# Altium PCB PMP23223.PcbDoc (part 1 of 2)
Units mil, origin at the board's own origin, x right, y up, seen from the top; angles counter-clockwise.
Board outline 2732.07 x 1574.8 mil, 4 copper layers (Top Layer 1, GND plane, Bottom Layer, Bottom Layer 1), stack 70.356 mil thick; 100 components, 33 nets, 239 pads, 115 vias.
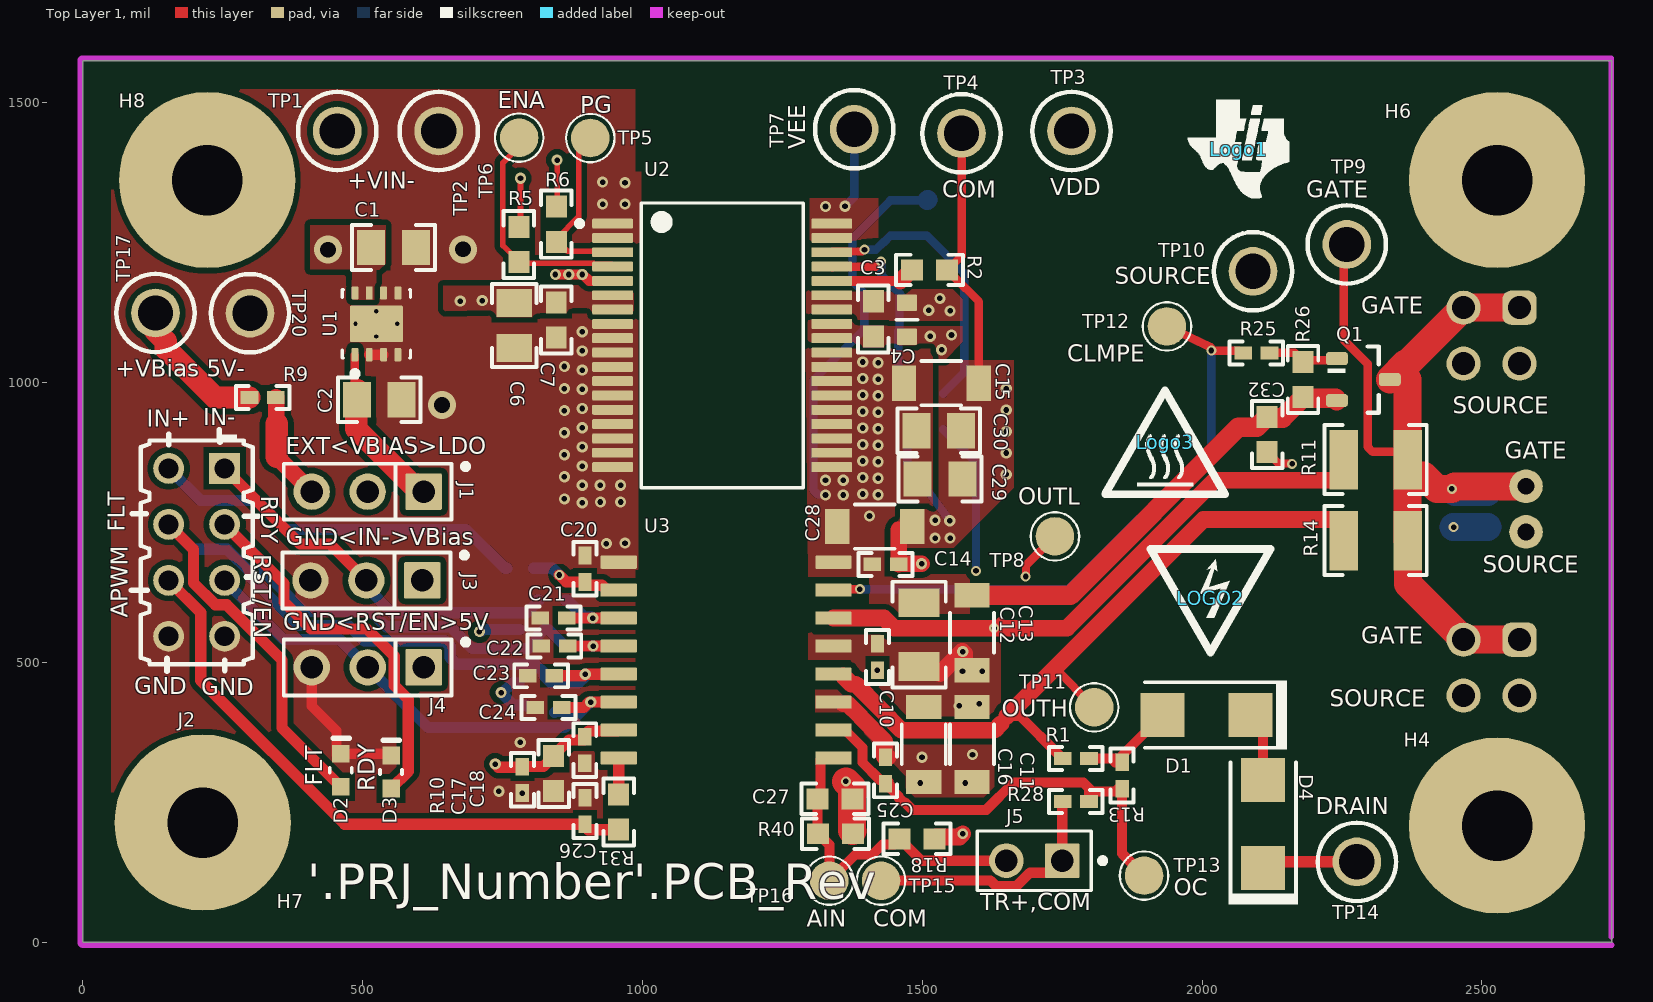
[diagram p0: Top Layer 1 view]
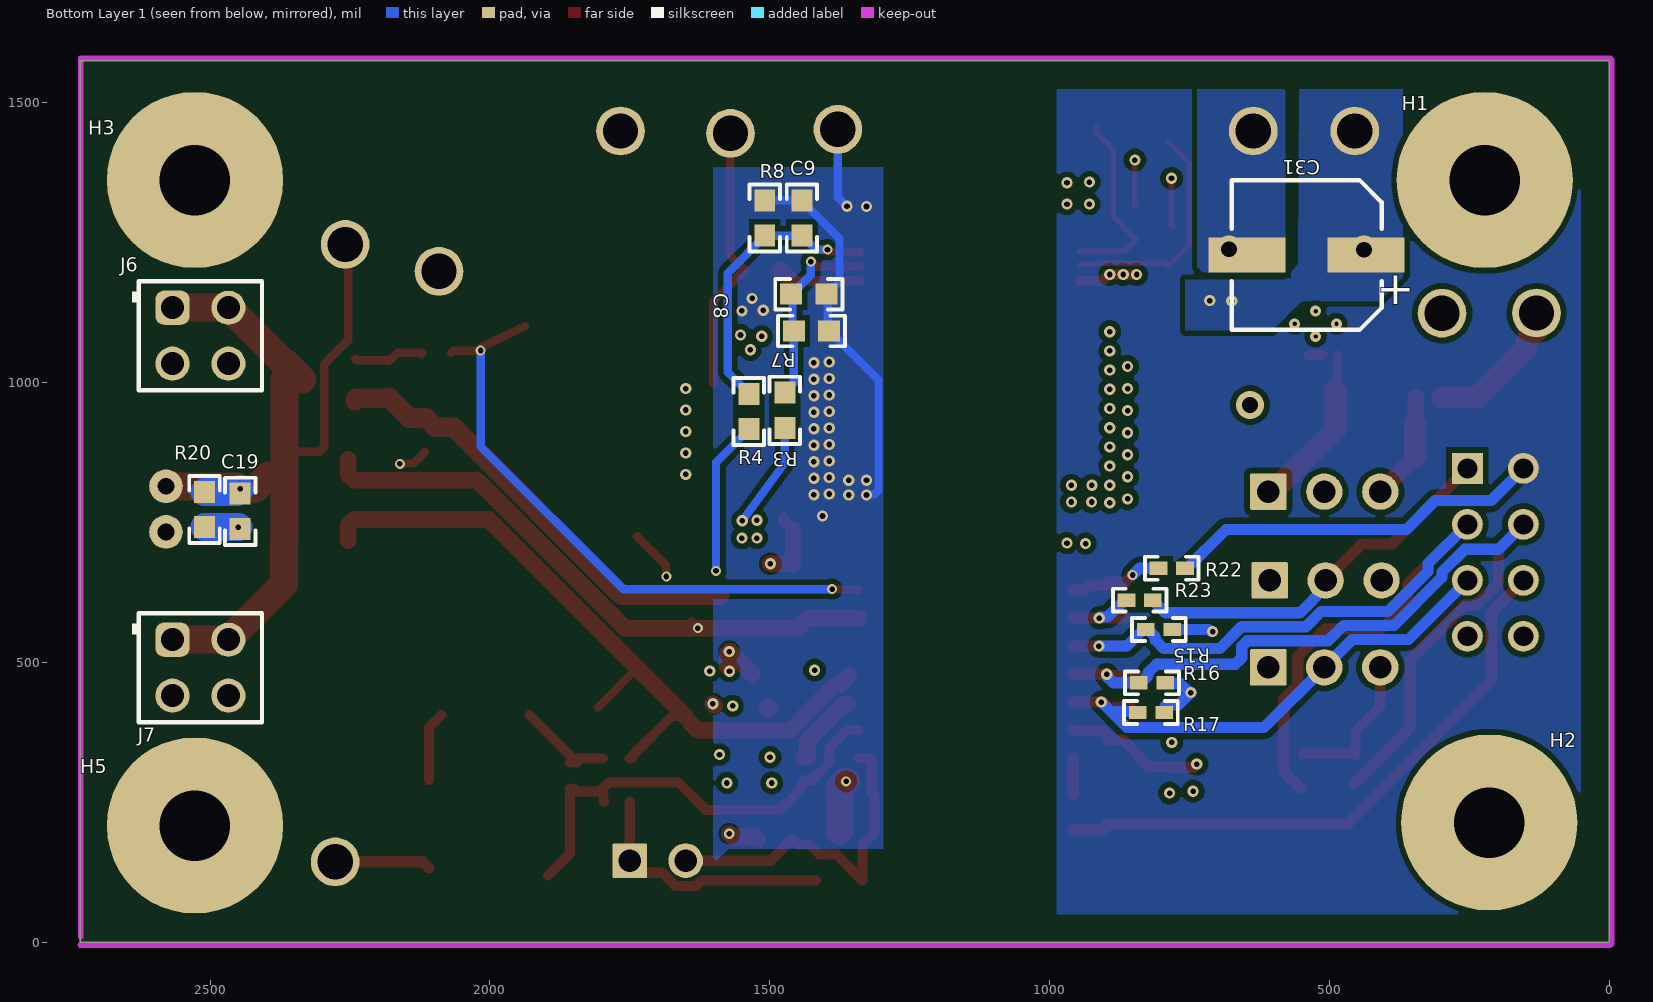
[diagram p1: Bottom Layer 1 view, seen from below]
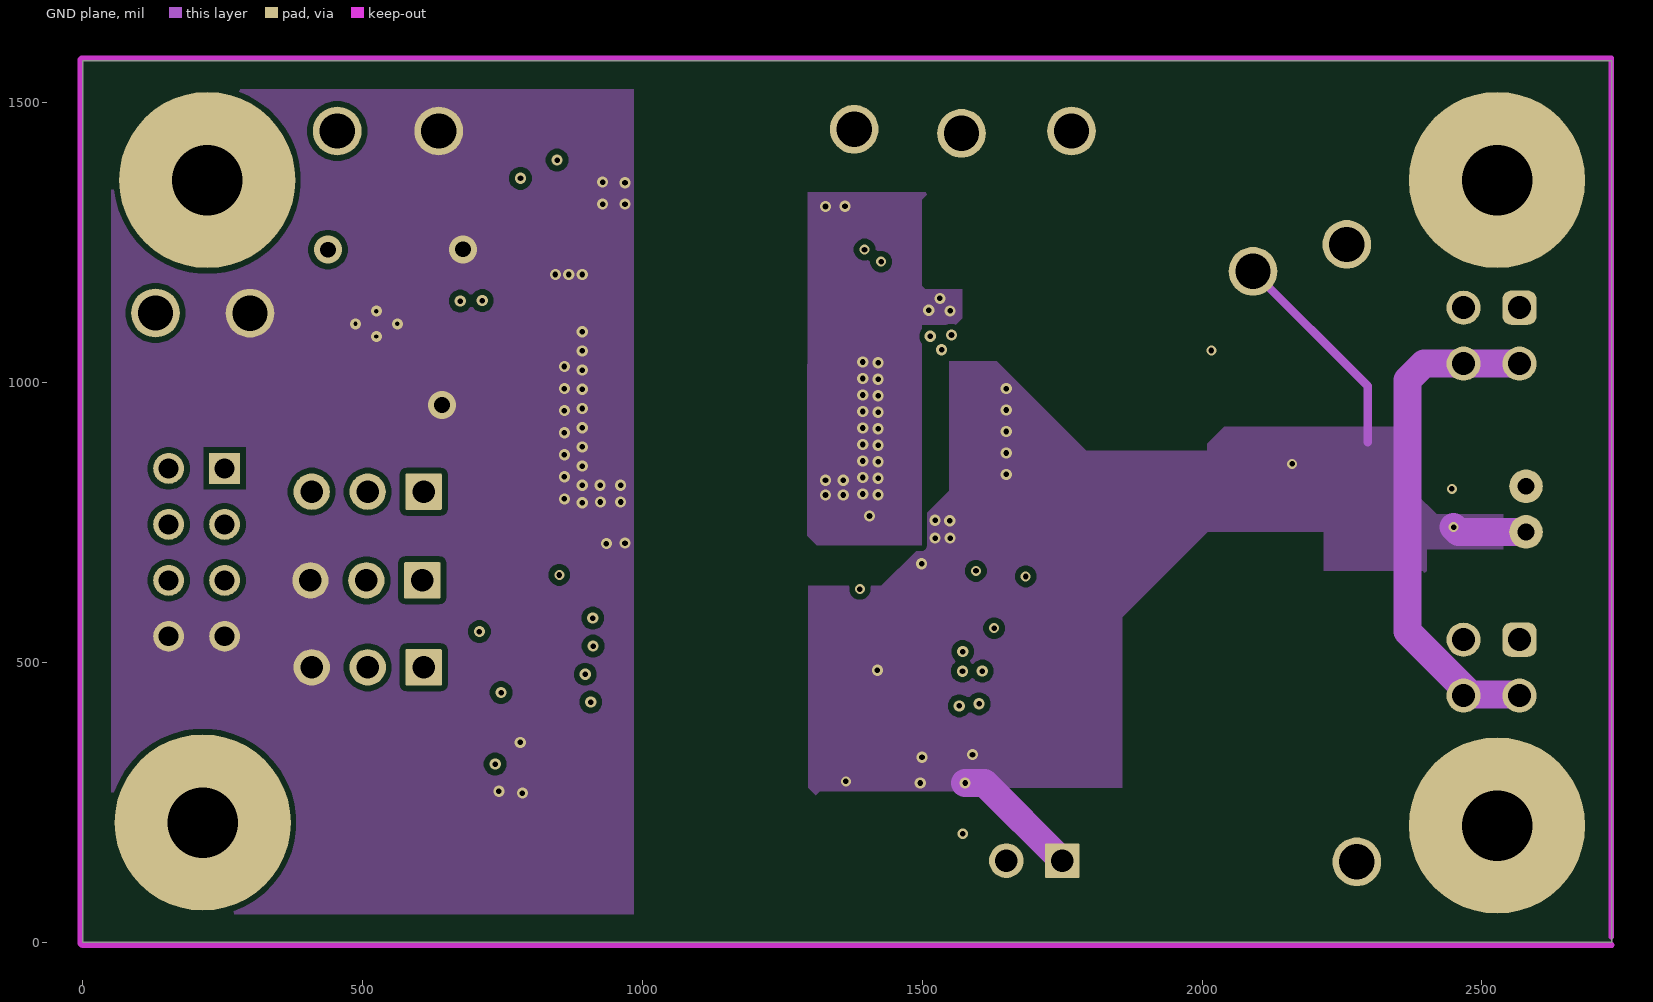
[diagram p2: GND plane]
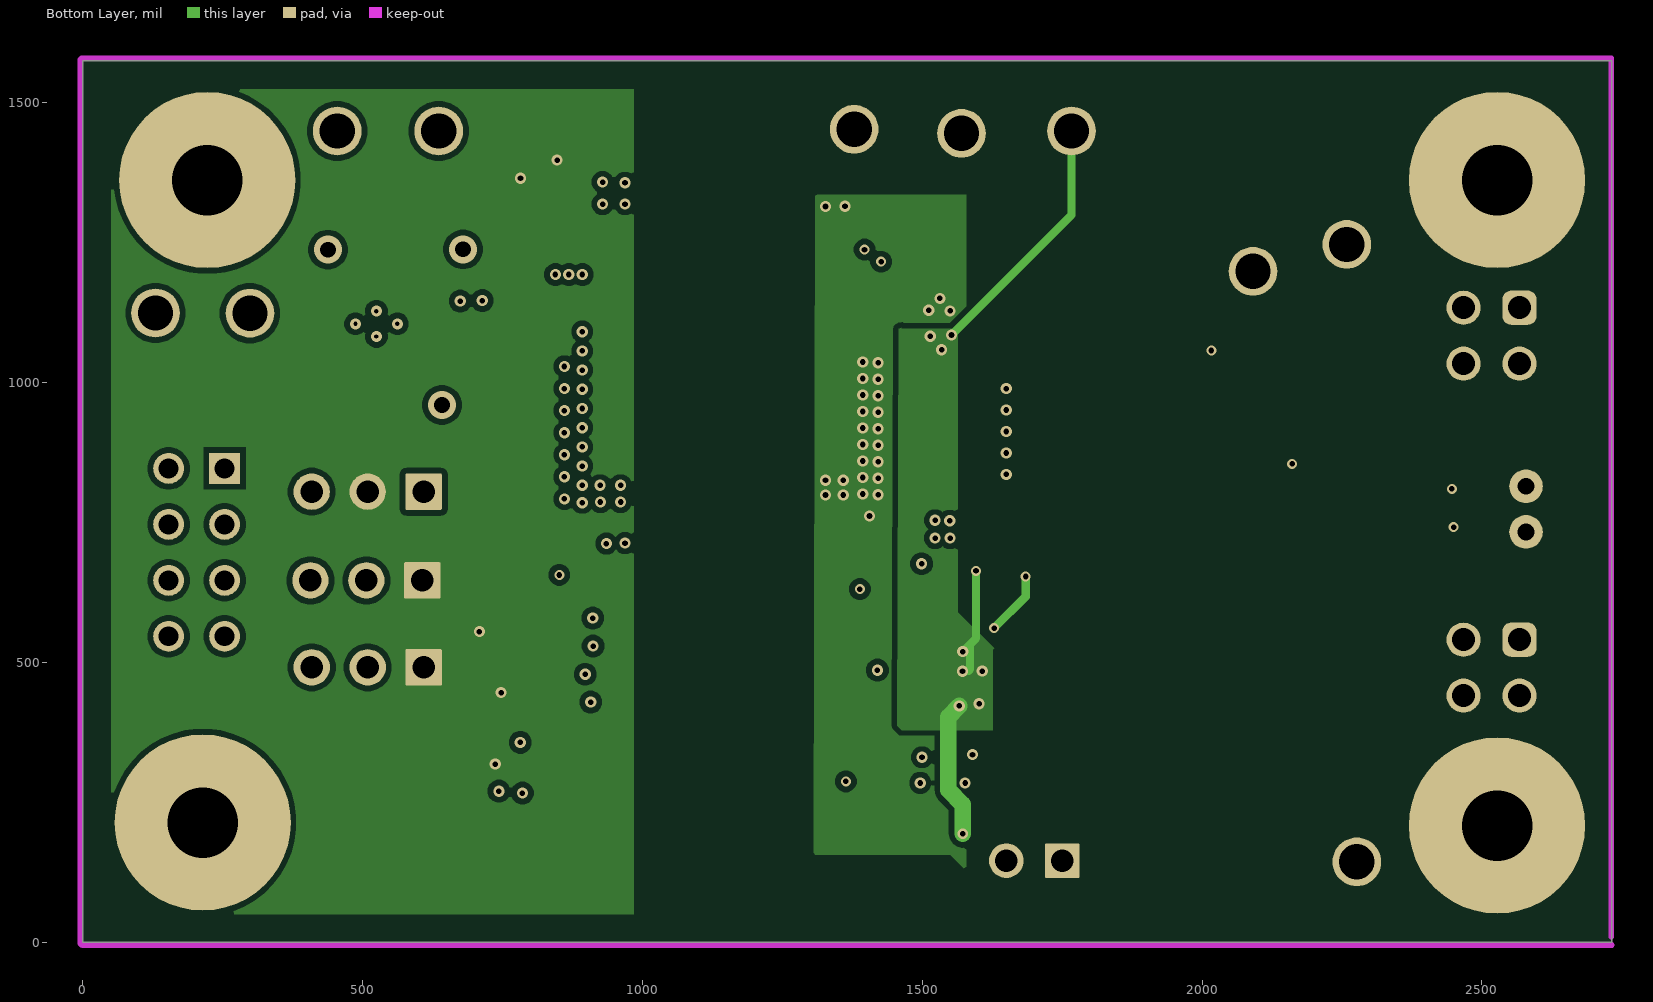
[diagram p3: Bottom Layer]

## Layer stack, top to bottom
Top Solder: solder mask 0.4, Solder Resist, Dk 3.5
Top Layer 1: signal copper 1.378
Dielectric 1: prepreg 2.8, PP-006, Dk 4.1
GND plane: signal copper 1.4
Dielectric1: core 59.2, FR-4 High Tg, Dk 4.8
Bottom Layer: signal copper 1.4
Dielectric 2: prepreg 2.8, PP-006, Dk 4.1
Bottom Layer 1: signal copper 1.378
Bottom Solder: solder mask 0.4, Solder Resist, Dk 3.5

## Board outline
0,0 0,1574.8 2732.07,1574.8 2732.07,0

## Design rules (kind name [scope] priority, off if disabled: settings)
AcuteAngle [All] p1: minimum=4.50000000000000E+0001 checktracksonly=TRUE
AssemblyTestPointUsage [All] p1: valid=2
BoardOutlineClearance BoardOutlineClearance_MountingHoles [OnCopper and InComponentClass('Mounting Holes')] p1: gap=39.37 ignorepadtopadclearanceinfootprint=FALSE
BoardOutlineClearance BoardOutlineClearance_Poly [OnCopper and IsPoly] p2: gap=50 ignorepadtopadclearanceinfootprint=FALSE
BoardOutlineClearance [OnCopper and Not InComponentClass('Logo') and not InComponentClass('FiducialMark') and not InRegion(1000,500,4000,800) and not InPoly] p3: gap=75 ignorepadtopadclearanceinfootprint=FALSE
Clearance Clearance_Keepouts [((IsTrack Or IsArc) And Not InPoly) And IsFree and IsKeepOut vs ((IsTrack Or IsArc) And Not InPoly) And IsFree and IsKeepOut] p1: gap=0 ignorepadtopadclearanceinfootprint=FALSE
Clearance Clearance_Poly [InPolygon] p2: gap=10 ignorepadtopadclearanceinfootprint=TRUE
Clearance Clearance_FiducialMark [IsKeepOut and InComponentClass('FiducialMark') vs IsPad and InComponentClass('FiducialMark')] p3: gap=0 ignorepadtopadclearanceinfootprint=FALSE
Clearance [All] p4: gap=5 ignorepadtopadclearanceinfootprint=TRUE
ComponentClearance ComponentClearance_2 [InComponent('NT*')] p1: gap=0 collisioncheckmode=3 verticalgap=0 showdistances=FALSE
ComponentClearance ComponentClearance_MountingHoles_FiducialMarks [InComponentClass('Mounting Holes') vs InComponentClass('FiducialMark')] p2: gap=50 collisioncheckmode=3 verticalgap=10 showdistances=FALSE
ComponentClearance ComponentClearance_Shunt [InComponentClass('Header') vs InComponentClass('Shunt')] p3: gap=0 collisioncheckmode=3 verticalgap=0 showdistances=FALSE
ComponentClearance ComponentClearance_Logo [InComponentClass('Logo')] p4: gap=50 collisioncheckmode=3 verticalgap=10 showdistances=FALSE
ComponentClearance ComponentClearance_ScrewToNut [(HasFootprint('NY PMS 440 0025 PH')) vs (HasFootprint('Keystone_1902C'))] p5: gap=5 collisioncheckmode=3 verticalgap=10 showdistances=FALSE
ComponentClearance ComponentClearance_MountingHoles [InComponentClass('Mounting Holes')] p6: gap=250 collisioncheckmode=3 verticalgap=100000 showdistances=FALSE
ComponentClearance ComponentClearance_SmallPassives [HasFootprint('0201*') or HasFootprint('0402*') or HasFootprint('0508') or HasFootprint('0603*') or HasFootprint('0612') or HasFootprint('0805*') or HasFootprint('0815*') or HasFootprint('0830*') or HasFootprint('1206*') or HasFootprint('1210*') or HasFootprint('1808*') or HasFootprint('1812*') or HasFootprint('1825*') or HasFootprint('2010*') or HasFootprint('2220*') or HasFootprint('2225*') or HasFootprint('2512*') or HasFootprint('2728*') or HasFootprint('3518*') vs HasFootprint('0201*') or HasFootprint('0402*') or HasFootprint('0508') or HasFootprint('0603*') or HasFootprint('0612') or HasFootprint('0805*') or HasFootprint('0815*') or HasFootprint('0830*') or HasFootprint('1206*') or HasFootprint('1210*') or HasFootprint('1808*') or HasFootprint('1812*') or HasFootprint('1825*') or HasFootprint('2010*') or HasFootprint('2220*') or HasFootprint('2225*') or HasFootprint('2512*') or HasFootprint('2728*') or HasFootprint('3518*')] p7: gap=14.96 collisioncheckmode=3 verticalgap=10 showdistances=FALSE
ComponentClearance ComponentClearance_THtoSMT [IsThruComponent vs IsSMTComponent] p8: gap=40 collisioncheckmode=3 verticalgap=30 showdistances=FALSE
ComponentClearance ComponentClearance_THtoTH [IsThruComponent vs IsThruComponent] p9: gap=30 collisioncheckmode=3 verticalgap=30 showdistances=FALSE
ComponentClearance [All] p10: gap=30 collisioncheckmode=3 verticalgap=10 showdistances=FALSE
DiffPairsRouting [All] p1: maxlimit=100 minlimit=10 mostfreqgap=10 toplayer_minwidth=6 toplayer_maxwidth=15 toplayer_prefwidth=6 midlayer1_minwidth=6 midlayer1_maxwidth=15 midlayer1_prefwidth=6 midlayer2_minwidth=6 midlayer2_maxwidth=15 midlayer2_prefwidth=6 bottomlayer_minwidth=6 bottomlayer_maxwidth=15 bottomlayer_prefwidth=6 maxuncoupledlength=1000
FabricationTestPointUsage TestPointUsage [All] p1: valid=2 allowmultiple=FALSE
FabricationTestpoint Testpoint [All] p1: side=3 testpointundercomponent=TRUE minsize=40 maxsize=100 preferedsize=60 minholesize=0 maxholesize=40 preferedholesize=32 testpointgrid=1 allowsidetop=TRUE allowsidebottom=TRUE usegrid=TRUE gridtolerance=0.01
FanoutControl Fanout_LCC [IsLCC] p1: bgadir=Out bgaviamode=Centered fanoutstyle=Auto fanoutdirection=Alternating viagrid=1 // Fanout_LCC (Default Rule)
FanoutControl Fanout_BGA [IsBGA] p2: bgadir=Out bgaviamode=Centered fanoutstyle=Auto fanoutdirection=Alternating viagrid=1 // Fanout_BGA (Default Rule)
FanoutControl Fanout_Default [All] p4: bgadir=Out bgaviamode=Centered fanoutstyle=Auto fanoutdirection=Alternating viagrid=1 // Fanout_Default (Default Rule)
FanoutControl Fanout_Small [(CompPinCount < 5)] p5: bgadir=Out bgaviamode=Centered fanoutstyle=Auto fanoutdirection=OutThenIn viagrid=1 // Fanout_Small (Default Rule)
HoleSize [All] p1: absolutevalues=TRUE maxlimit=270 minlimit=7.87 maxpercent=80.000 minpercent=20.000
MinimumAnnularRing MinimumAnnularRing_ThermalPadVias [IsVia and InAnyComponent] p1: minimumring=5.91
MinimumAnnularRing [All] p2: minimumring=4
MinimumSolderMaskSliver MinimumSolderMaskSliver_Logo [InComponentClass('Logo') vs InComponentClass('Logo')] p1: minsoldermaskwidth=0.7
MinimumSolderMaskSliver [All] p2: minsoldermaskwidth=1.5
NetsToIgnore [InNet('No Net')] p1 off:
PlaneClearance [All] p1: clearance=10
PlaneConnect [All] p1: planeconnectstyle=Relief reliefexpansion=10 reliefentries=4 reliefconductorwidth=10 reliefairgap=10
PolygonConnect [All] p1: connectstyle=Direct reliefconductorwidth=10 reliefentries=4 polygonreliefangle="90 Angle" airgapwidth=10
RoutingVias ThermalPadVias [IsVia and InAnyComponent] p1: holewidth=7.87 width=19.68 viastyle="Through Hole" minholewidth=7.87 minwidth=19.68 maxholewidth=12.99 maxwidth=23.62
RoutingVias [All] p2: holewidth=10 width=18 viastyle="Through Hole" minholewidth=10 minwidth=18 maxholewidth=40 maxwidth=64
SMDEntry [All] p1 off: side=TRUE corner=TRUE anyangle=FALSE
SMDToCorner [All] p1 off: distance=50000
SilkToBoardRegionClearance [Not ((IsComment or IsDesignator) And (Hide <> 'False')) and not InRegion(1000,500,4000,800)] p1:
SilkToSilkClearance SilkToSilkClearance_Pb-FreeLogo [(HasFootprint('Pb-Free_Overlay_Medium') OR HasFootprint('Pb-Free_Overlay_Small')) vs (HasFootprint('Pb-Free_Overlay_Medium') OR HasFootprint('Pb-Free_Overlay_Small'))] p1: silktosilkclearance=0
SilkToSilkClearance [All] p2: silktosilkclearance=0
SilkToSolderMaskClearance SilkToComponentPadClearance [(IsPad or IsFill or IsRegion) and InAnycomponent] p1: minsilkscreentomaskgap=3 clearancetoexposedcopper=TRUE
SilkToSolderMaskClearance "Silk to Solder Mask Opening" [All] p2: minsilkscreentomaskgap=3.94 clearancetoexposedcopper=FALSE
SolderMaskExpansion [All] p1: expansion=4 istentingtop=FALSE
UnRoutedNet [All] p1: checkbadconnections=TRUE
Width [All] p1: maxlimit=100 minlimit=5 preferedwidth=10 checkconnectedcopper=TRUE
13 further rules are at their usual default settings.

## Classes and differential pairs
component class Logo: Logo1
component class "Mounting Holes": H4 H6 H7 H8
component class Header: J1 J2 J3 J4

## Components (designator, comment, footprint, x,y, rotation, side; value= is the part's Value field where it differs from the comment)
C1 "CGA4J3X7R1H105K125AB" 0805_HV 554.98,1241.36 r0 top value=1uF
C2 "GCJ21BR71A106KE01L" 0805_HV 529.53,969.45 r0 top value=10uF
C3 "CGA3E2X7R1H104K080AA" 0603 1412.48,1113.91 r90 top value=0.1uF
C4 "GRT188C8YA225KE13D" FP-GRT188C8YA225KE13D_0603-MFG 1472.5,1112.41 r270 top value=2.2µF
C6 "CGA4J1X7R1V475K125AC" 0805_HV 770.77,1101.92 r270 top value=4.7uF
C7 "CGA3E2X7R1H104K080AA" 0603 845.76,1112.1 r270 top value=0.1uF
C8 "GRM188R72A331KA01D" 0603 1429.96,1158.21 r180 bottom value=330pF
C9 "GRM188R72A331KA01D" 0603 1442.22,1294.24 r90 bottom value=330pF
C10 "GCM155R71C104KA55D" 0402 1419.72,509.76 r270 top value=0.1uF
C11 "CL31B106KBHNNNE" 1206_180 1588.82,353.47 r270 top value=10uF
C12 "C1206C104J5RACTU" 1206 1494.1,549.68 r90 top value=0.1uF
C13 "C3216X7R1H475K160AC" 1206_180 1588.82,552.94 r90 top value=4.7uF
C14 "GCM155R71C104KA55D" 0402 1434.13,675.29 r180 top value=0.1uF
C15 "CL31B106KBHNNNE" 1206_180 1534.03,999.06 r180 top value=10uF
C16 "CL31B106KBHNNNE" 1206_180 1502.61,353.47 r270 top value=10uF
C17 "C1608X7R1A155K080AC" 0603 841.02,301.43 r90 top value=1.5uF
C18 "Capacitor" 0402 896.78,343.35 r270 top value=0.1uF
C19 "C1608X7R1H103K080AA" 0603 2446.26,770.01 r270 bottom value=0.01uF
C20 "CC0402JRNPO9BN101" 0402 897.16,667.4 r90 top value=100pF
C21 "CC0402JRNPO9BN101" 0402 840.91,579.18 r180 top value=100pF
C22 "CC0402JRNPO9BN101" 0402 842.4,529.18 r180 top value=100pF
C23 "CC0402JRNPO9BN101" 0402 818.77,476.14 r180 top value=100pF
C24 "CC0402JRNPO9BN101" 0402 831.98,419.7 r180 top value=100pF
C25 "GRM1555C1H241JA01D" 0402 1434.13,307.02 r90 top value=240pF
C26 "GRM155R71C222KA01D" 0402 897.16,234.5 r90 top value=2200pF
C27 "SR0603X7R103K1NT95(F)#M123A" 0603 1343.93,256.15 r0 top value=0.01uF
C28 "C3216X7R1H475K160AC" 1206_180 1415.02,742.71 r180 top value=4.7uF
C29 "GRT21BR61E226ME13L" 0805_HV 1531.43,827.68 r180 top value=22uF
C30 "GRT21BR61E226ME13L" 0805_HV 1529.3,914.01 r180 top value=22uF
C31 "HHXC250ARA470MF61G" HXB_F61 540.33,1228.05 r0 bottom value=47uF
C32 "CGA3E2X7R1H104K080AA" 0603 2116.2,907.46 r270 top value=0.1uF
D1 "STTH112A" SMA 2007.82,406.02 r180 top value=1200V
D2 "LG L29K-G2J1-24-Z" "LG L29K_GREEN" 460.79,307.33 r90 top value=Green
D3 "LG L29K-G2J1-24-Z" "LG L29K_GREEN" 550.59,304.19 r90 top value=Green
D4 "STTH112A" SMA 2108.99,211.4 r90 top value=1200V
H1 "1902C" Keystone_1902C 222.12,1361.91 r180 bottom
H2 "1902C" Keystone_1902C 214.06,213.83 r180 bottom
H3 "1902C" Keystone_1902C 2527.04,1361.97 r180 bottom
H4 "NY PMS 440 0025 PH" "NY PMS 440 0025 PH" 2527.04,208.41 r0 top
H5 "1902C" Keystone_1902C 2527.04,208.41 r180 bottom
H6 "NY PMS 440 0025 PH" "NY PMS 440 0025 PH" 2527.04,1361.97 r0 top
H7 "NY PMS 440 0025 PH" "NY PMS 440 0025 PH" 214.06,213.83 r0 top
H8 "NY PMS 440 0025 PH" "NY PMS 440 0025 PH" 222.12,1361.91 r0 top
J1 "HTSW-103-07-G-S" Samtec_HTSW-103-07-G-S 508.78,805.07 r180 top
J2 "802-10-008-10-001000" Mill-Max_802-10-008-10-001000 203.09,696.63 r270 top
J3 "HTSW-103-07-G-S" Samtec_HTSW-103-07-G-S 506.48,646.63 r180 top
J4 "HTSW-103-07-G-S" Samtec_HTSW-103-07-G-S 508.87,491.23 r180 top
J5 "2011-1X02G00SB" FP-2011-1X02G00SB_HDR-MFG 1699.98,145.62 r180 top
J6 "SSW-102-01-G-D" Samtec_SSW-102-01-x-D 2517.13,1083.88 r180 bottom
J7 "SSW-102-01-G-D" Samtec_SSW-102-01-x-D 2517.13,490.63 r180 bottom
Logo1 "Texas Instruments" TI_Symbol_Overlay_Small 2064.98,1416.97 r0 top
LOGO2 "DANGER HIGH VOLTAGE" IEC_HighVoltage_Small 2014.88,614.96 r180 top
Logo3 "CAUTION HOT SURFACE" IEC_HotSurface_Small 1933.67,893.49 r0 top
Q1 "SI2318CDS-T1-GE3" SOT-23 2288.03,1005.51 r0 top value=40V
R1 "RMCF0402FT2K20" 0402 1774.16,328.31 r0 top value=2.20k
R2 "CRCW0603470RJNEA" 0603 1512.72,1201.36 r180 top value=470
R3 "RT0603BRD0713K2L" 0603 1472.89,950.46 r270 bottom value=13.2k
R4 "RT0603DRE0777K7L" 0603 1537.22,948.45 r270 bottom value=77.7k
R5 "CRCW060310K0FKEA" 0603 779.12,1246.75 r90 top value=10.0k
R6 "CRCW060310K0FKEA" 0603 845.94,1283.17 r270 top value=10.0k
R7 "ERJ-3EKF2202V" 0603 1425.27,1092.26 r0 bottom value=22.0k
R8 "CRCW060310K0FKEA" 0603 1508.68,1294.24 r270 bottom value=10.0k
R9 "CRCW04023R30JNED" 0402 321.14,973.52 r0 top value=3.3
R10 "RMCF0402FT10K0" 0402 785.18,290.2 r90 top value=10.0k
R11 "RC1210FR-072R2L" 1210 2310.12,862.43 r0 top value=2.20
R13 "CRCW04026K04FKED" 0402 1857.07,297.94 r270 top value=6.04k
R14 "RC1210FR-072R2L" 1210 2310.12,717.8 r0 top value=2.20
R15 "CRCW04024K99FKED" 0402 804.41,558.68 r180 bottom value=4.99k
R16 "CRCW04024K99FKED" 0402 816.64,463.58 r180 bottom value=4.99k
R17 "PCF0402-12-10KBT1" 0402 818.77,410.29 r180 bottom value=10.0k
R18 "RT0603DRE0725K8L" 0603 1490.22,184.53 r0 top value=25.8k
R20 "CRCW060310K0JNEA" 0603 2509.84,773.22 r90 bottom value=10k
R22 "Resistor" 0402 781.48,668.28 r180 bottom value=100
R23 "Resistor" 0402 838.69,611.14 r180 bottom value=100
R25 "ERJ-2GE0R00X" 0402 2096.75,1053.1 r180 top value=0
R26 "M55342K12B10E0T" 0603 2180.22,1005.51 r90 top value=10.0k
R28 "CRCW0402499RFKED" 0402 1774.16,251.23 r180 top value=499
R31 "RT0603DRE0720KL" 0603 957.28,232.53 r270 top value=20.0k
R40 "CRCW06036K19FKEA" 0603 1344.69,193.86 r180 top value=6.19k
TP1 "VIN" Keystone5005 454.38,1449.65 r0 top
TP2 "GND" Keystone5006 635.75,1449.65 r0 top
TP3 "5005" Keystone5005 1766.55,1449.65 r0 top
TP4 "5006" Keystone5006 1570.09,1445.54 r0 top
TP5 "PG" Mill-Max_0508-0-00-15-00-00-03-0 906.6,1437.11 r90 top
TP6 "ENA" Mill-Max_0508-0-00-15-00-00-03-0 779.41,1437.76 r0 top
TP7 "5007" Keystone5007 1378.21,1452.76 r0 top
TP8 "OUTL" Mill-Max_0508-0-00-15-00-00-03-0 1736.91,725.25 r0 top
TP9 "5009" Keystone5009 2258.41,1247.03 r0 top
TP10 "5006" Keystone5006 2090.87,1198.94 r90 top
TP11 "OUTH" Mill-Max_0508-0-00-15-00-00-03-0 1807.03,419.7 r90 top
TP12 "CLME" Mill-Max_0508-0-00-15-00-00-03-0 1937.08,1100.43 r180 top
TP13 "OC" Mill-Max_0508-0-00-15-00-00-03-0 1896.19,119.08 r90 top
TP14 "5008" Keystone5008 2276.41,143.65 r90 top
TP15 "COM" Mill-Max_0508-0-00-15-00-00-03-0 1426.18,110.01 r90 top
TP16 "AIN" Mill-Max_0508-0-00-15-00-00-03-0 1333.73,110.01 r90 top
TP17 "VBIAS" Keystone5005 129.6,1124.43 r0 top
TP20 "GND" Keystone5006 298.36,1124.02 r0 top
U1 "TPS7B8450QWDRBRQ1" DRB0008J-MFG 524.38,1104.99 r90 top
U2 "UCC14240DWNQ1" DWN0036-MFG 1142.32,1066.6 r0 top
U3 "UCC21732QDWRQ1" DW0016B_HV 1149.21,504.18 r180 top

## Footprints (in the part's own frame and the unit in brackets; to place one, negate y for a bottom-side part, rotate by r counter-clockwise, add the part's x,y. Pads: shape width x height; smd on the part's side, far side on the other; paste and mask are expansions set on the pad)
0402 [mm] "0402 from SM-752 data"
  rect 0.8x0.6 smd: 1(-0.6,0) 2(0.6,0)
  silkscreen extent -1.22,-0.52 1.22,0.52, body extent -0.55,-0.3 0.55,0.3, height 0.6
0603 [mm] "0603 from SM-752 data"
  rect 1x0.95 smd: 1(-0.8,0) 2(0.8,0)
  silkscreen extent -1.52,-0.69 1.52,0.69, body extent -0.87,-0.47 0.87,0.47, height 1
0805_HV [mil] "0805 with 30mil clearance between pads"
  rect 50x63 smd: 1(-40,0) 2(40,0)
  silkscreen extent -74,-40 74,40, body extent -43,-29 43,29, height 57
1206 [mm] "1206 from SM-752 data"
  rect 1.3x1.85 smd: 1(-1.45,0) 2(1.45,0)
  silkscreen extent -2.4,-1.21 2.4,1.21, body extent -1.7,-0.9 1.7,0.9, height 1.35
1206_180 [mm] "1206_180"
  rect 1.1x1.6 smd: 1(-1.7,0) 2(1.7,0)
  silkscreen extent -0.9,-1 0.9,1, body extent -1.75,-0.95 1.75,0.95, height 1.8
1210 [mm] "1210 from SM-752 data"
  rect 1.3x2.7 smd: 1(-1.45,0) 2(1.45,0)
  silkscreen extent -2.32,-1.57 2.32,1.57, body extent -1.7,-1.35 1.7,1.35, height 1.35
DRB0008J-MFG [mm]
  rrect32% 0.6x0.31 smd paste+0 mask+0: 1(-1.4,0.975) 2(-1.4,0.325) 3(-1.4,-0.325) 4(-1.4,-0.975) 5(1.4,-0.975) 6(1.4,-0.325) 7(1.4,0.325) 8(1.4,0.975)
  rrect6% 1.65x2.4 smd paste-1000 mask+0: 9(0,0)
  silkscreen extent -2.38,-1.55 1.55,1.55, body extent -1.8,-1.65 1.8,1.65, height 0.25
DW0016B_HV [mm] "SOIC-16, HV/isolation option"
  rrect17% 1.65x0.6 smd: 1(-4.875,4.445) 2(-4.875,3.175) 3(-4.875,1.905) 4(-4.875,0.635) 5(-4.875,-0.635) 6(-4.875,-1.905) 7(-4.875,-3.175) 8(-4.875,-4.445) 9(4.875,-4.445) 10(4.875,-3.175) 11(4.875,-1.905) 12(4.875,-0.635) 13(4.875,0.635) 14(4.875,1.905) 15(4.875,3.175) 16(4.875,4.445)
  body extent -5.17,-5.15 5.17,5.15, height 2.59
DWN0036-MFG [mm]
  rrect22% 1.85x0.45 smd paste+0 mask+0: 1(-4.975,5.525) 2(-4.975,4.875) 3(-4.975,4.225) 4(-4.975,3.575) 5(-4.975,2.925) 6(-4.975,2.275) 7(-4.975,1.625) 8(-4.975,0.975) 9(-4.975,0.325) 10(-4.975,-0.325) 11(-4.975,-0.975) 12(-4.975,-1.625) 13(-4.975,-2.275) 14(-4.975,-2.925) 15(-4.975,-3.575) 16(-4.975,-4.225) 17(-4.975,-4.875) 18(-4.975,-5.525) 19(4.975,-5.525) 20(4.975,-4.875) 21(4.975,-4.225) 22(4.975,-3.575) 23(4.975,-2.925) 24(4.975,-2.275) 25(4.975,-1.625) 26(4.975,-0.975) 27(4.975,-0.325) 28(4.975,0.325) 29(4.975,0.975) 30(4.975,1.625) 31(4.975,2.275) 32(4.975,2.925) 33(4.975,3.575) 34(4.975,4.225) 35(4.975,4.875) 36(4.975,5.525)
  silkscreen extent -6.6,-6.47 3.67,6.47, body extent -6,-6.57 6,6.57, height 0.25
FP-2011-1X02G00SB_HDR-MFG [mm]
  rrect6% 1.57x1.57 hole 1.02 paste-1000 mask+0: 1(-1.27,0)
  round 1.57 hole 1.02 paste-1000 mask+0: 2(1.27,0)
  silkscreen extent -3.22,-1.35 2.59,1.35, body extent -2.69,-1.45 2.69,1.45, height 0.25
FP-GRT188C8YA225KE13D_0603-MFG [mm]
  rrect13% 0.75x0.9 smd paste+0 mask+0: 1(-0.775,0) 2(0.775,0)
  silkscreen extent 0,-0.5 0,0.5, body extent -1.25,-0.6 1.25,0.6, height 0.25
HXB_F61 [mm] "SMD, 2-Leads, Dia 6.3mm"
  rect 3.5x1.6 smd: 1(-2.7,0) 2(2.7,0)
  silkscreen extent -3.4,-3.4 3.4,3.4, body extent -3.4,-3.4 3.4,3.4, height 6.11
IEC_HighVoltage_Small [mil]
  silkscreen extent -107,-88 107,97
IEC_HotSurface_Small [mil]
  silkscreen extent -107,-93 107,92
Keystone5005 [mil] "Keystone Compact loops"
  round 87 hole 63: 1(0,0)
  silkscreen extent -70,-70 70,70, body extent -63,-63 62,63, height 225
Keystone5006 [mil] "Keystone Compact loops"
  round 87 hole 63: 1(0,0)
  silkscreen extent -70,-70 70,70, body extent -63,-63 62,63, height 225
Keystone5007 [mil] "Keystone Compact loops"
  round 87 hole 63: 1(0,0)
  silkscreen extent -70,-70 70,70, body extent -63,-63 62,63, height 225
Keystone5008 [mil] "Keystone Compact loops"
  round 87 hole 63: 1(0,0)
  silkscreen extent -70,-70 70,70, body extent -63,-63 62,63, height 225
Keystone5009 [mil] "Keystone Compact loops"
  round 87 hole 63: 1(0,0)
  silkscreen extent -70,-70 70,70, body extent -63,-63 62,63, height 225
Keystone_1902C [mil] "Hex Standoff, 4-40 threaded, nylon"
  round 1 on Mech4: 0(0,0)
  body extent -145,-126 146,126, height 501
"LG L29K_GREEN" [mm] "OSRAM"
  rect 0.8x0.8 smd paste-0.4: 1(-0.75,0) 2(0.75,0)
  silkscreen extent -0.1,-0.5 1.45,0.5, body extent -0.9,-0.45 0.9,0.45, height 0.67
Mill-Max_0508-0-00-15-00-00-03-0 [mm] "PCB Pin, 20mil Dia, TH"
  round 1.75 smd: 1(0,0)
  silkscreen extent -1.1,-1.1 1.1,1.1, body extent -0.72,-0.74 0.74,0.74, height 4.44
Mill-Max_802-10-008-10-001000 [mm] "Header, 2.54 mm, 4x2, TH"
  rect 1.4x1.4 hole 0.9: 1(-3.81,1.27)
  round 1.4 hole 0.9: 2(-3.81,-1.27) 3(-1.27,1.27) 4(-1.27,-1.27) 5(1.27,1.27) 6(1.27,-1.27) 7(3.81,1.27) 8(3.81,-1.27)
  silkscreen extent -5.36,-2.54 5.08,2.54, body extent -5.08,-2.54 5.08,2.54, height 8.11
"NY PMS 440 0025 PH" [mm] "4-40 nylon screw and mounting hole"
  round 8 hole 3.2: 1(0,0)
  body extent -3.3,-3.3 3.3,3.3, height 2.69
Samtec_HTSW-103-07-G-S [mm] "Samtec 100mil, 1x3, 230 mil above insulator"
  rrect6% 1.65x1.65 hole 1.016: 1(-2.54,0)
  round 1.65 hole 1.016: 2(0,0) 3(2.54,0)
  silkscreen extent -4.57,-1.27 3.81,1.27, body extent -3.81,-1.27 3.81,1.27, height 8.38
Samtec_SSW-102-01-x-D [mm] "Receptacle, 2.54mm, 2x2, TH"
  rrect50% 1.55x1.55 hole 1.04: 1(-1.27,1.27)
  round 1.55 hole 1.04: 2(-1.27,-1.27) 3(1.27,1.27) 4(1.27,-1.27)
  silkscreen extent -3.1,-2.48 2.79,2.48, body extent -2.79,-2.48 2.79,2.48, height 8.51
SMA [mm] "Molded Diode, 2-Leads, Body 4.3x2.6mm, IPC Medium Density, based on OnSemi component dimensions and land pattern"
  rect 2x2 smd: 1(-2,0) 2(2,0)
  silkscreen extent -3.66,-1.57 2.79,1.58, body extent -2.6,-1.3 2.6,1.3, height 2.42
SOT-23 [mm] "SOT23, 3-Leads, Body 2.9x1.3mm, Pitch 0.95mm, Lead Span 2.5mm, IPC Medium Density"
  rrect50% 1x0.6 smd: 1(-1.2,0.95) 2(-1.2,-0.95) 3(1.2,0)
  silkscreen extent -1.62,-1.5 0.7,1.5, body extent -1.16,-1.45 1.21,1.45, height 1
TI_Symbol_Overlay_Small [mil]
  silkscreen extent -90,-88 91,88

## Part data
C1: library part CMP-0007976-2, "CAP, CERM, 1 uF, 50 V, +/- 10%, X7R, AEC-Q200 Grade 1, 0805", Cap_Case=0805, Manufacturer=TDK, Supplier Part Number 1=445-6961-1-ND, TempCo=X7R, Tolerance_%=10%, Value1="0.008782 ohm", Value2=50V, ValueDisplayed=1uF
C2: library part CMP-0079153-1, "CAP, CERM, 10 µF, 10 V,+/- 10%, X7R, AEC-Q200 Grade 1, 0805", Cap_Case=0805, Manufacturer=MuRata, Supplier Part Number 1=490-12646-1-ND, TempCo=X7R, Tolerance_%=10%, Value2=10V, ValueDisplayed=10µF
C3 C7 C32: library part CMP-0007078-4, "CAP, CERM, 0.1 uF, 50 V, +/- 10%, X7R, AEC-Q200 Grade 1, 0603", Cap_Case=0603, Manufacturer=TDK, Supplier Part Number 1=445-5666-1-ND, TempCo=X7R, Tolerance_%=10%, Value1="0.0296 ohm", Value2=50V, ValueDisplayed=0.1uF
C4: library part CMP-0090212-1, "2.2µF ±10% 35V Ceramic Capacitor X6S 0603 (1608 Metric)", Digikey Part Number=490-12299-1-ND, Manufacturer=Murata, Mouser Part Number=81-GRT188C8YA225KE3D, Operating Temperature Range="-55°C to +105°C", TempCo=22%, Temperature Characteristic=X6S, Tolerance_%=10%, ValueDisplayed=2.2uF
C6: library part CMP-0007964-2, "CAP, CERM, 4.7 uF, 35 V, +/- 10%, X7R, AEC-Q200 Grade 1, 0805", Cap_Case=0805, Manufacturer=TDK, Supplier Part Number 1=810-CGA4J1X7R1V475K125AC, TempCo=X7R, Tolerance_%=10%, Value1="0.002346 ohm", Value2=35V, ValueDisplayed=4.7uF
C8 C9: library part CMP-0007478-4, "CAP, CERM, 330 pF, 100 V, +/- 10%, X7R, 0603", Cap_Case=0603, Manufacturer=MuRata, Supplier Part Number 1=490-1464-1-ND, TempCo=X7R, Tolerance_%=10%, Value1=Unknown, Value2=100V, ValueDisplayed=330pF
C10 C14: library part CMP-0006351-2, "CAP, CERM, 0.1 uF, 16 V, +/- 10%, X7R, 0402", Cap_Case=0402, Manufacturer=MuRata, Supplier Part Number 1=490-4759-2-ND, TempCo=X7R, Tolerance_%=10%, Value1=Unknown, Value2=16V, ValueDisplayed=0.1uF
C11 C15 C16: library part CMP-0008802-2, "CAP, CERM, 10 uF, 50 V, +/- 10%, X7R, 1206", Cap_Case=1206, Manufacturer=Samsung, Supplier Part Number 1=1276-6767-1-ND, TempCo=X7R, Tolerance_%=10%, Value1=Unknown, Value2=50V, ValueDisplayed=10uF
C12: library part CMP-0008584-2, "CAP, CERM, 0.1 uF, 50 V, +/- 5%, X7R, 1206", Cap_Case=1206, Manufacturer=Kemet, Supplier Part Number 1=399-1250-1-ND, TempCo=X7R, Tolerance_%=5%, Value1="0.059 ohm", Value2=50V, ValueDisplayed=0.1uF
C13 C28: library part CMP-0008702-2, "CAP, CERM, 4.7 uF, 50 V, +/- 10%, X7R, 1206", Cap_Case=1206_180, Manufacturer=TDK, Supplier Part Number 1=445-8032-1-ND, TempCo=X7R, Tolerance_%=10%, Value1="0.003158 ohm", Value2=50V, ValueDisplayed=4.7uF
C17: library part CMP-0007035-4, "CAP, CERM, 1.5 uF, 10 V, +/- 10%, X7R, 0603", Cap_Case=0603, Manufacturer=TDK, Supplier Part Number 1=445-14233-1-ND, TempCo=X7R, Tolerance_%=10%, Value1="0.004327 ohm", Value2=10V, ValueDisplayed=1.5uF
C18: library part CMP-0006659-2, "CAP, CERM, 0.1 uF, 25 V, +/- 10%, X7R, 0402", Cap_Case=0402, Manufacturer=MuRata, PartNumber=GRM155R71E104KE14D, Supplier Part Number 1=490-10698-1-ND, TempCo=X7R, Tolerance_%=10%, Value1=Unknown, Value2=25V, ValueDisplayed=0.1uF
C19: library part CMP-0007043-4, "CAP, CERM, 0.01 uF, 50 V, +/- 10%, X7R, 0603", Cap_Case=0603, Manufacturer=TDK, Supplier Part Number 1=445-1311-1-ND, TempCo=X7R, Tolerance_%=10%, Value1="0.0539 ohm", Value2=50V, ValueDisplayed=0.01uF
C20 C21 C22 C23 C24: library part CMP-0006303-2, "CAP, CERM, 100 pF, 50 V, +/- 5%, C0G/NP0, 0402", Cap_Case=0402, Manufacturer="Yageo America", Supplier Part Number 1=311-1024-1-ND, TempCo=C0G/NP0, Tolerance_%=5%, Value1=Unknown, Value2=50V, ValueDisplayed=100pF
C25: library part CMP-0006442-2, "CAP, CERM, 240 pF, 50 V, +/- 5%, C0G/NP0, 0402", Cap_Case=0402, Manufacturer=MuRata, Supplier Part Number 1=490-3233-1-ND, TempCo=C0G/NP0, Tolerance_%=5%, Value1=Unknown, Value2=50V, ValueDisplayed=240pF
C26: library part CMP-0006646-2, "CAP, CERM, 2200 pF, 16 V, +/- 10%, X7R, 0402", Cap_Case=0402, Manufacturer=MuRata, Supplier Part Number 1=GRM155R71C222KA01D-ND, TempCo=X7R, Tolerance_%=10%, Value1=Unknown, Value2=16V, ValueDisplayed=2200pF
C27: library part CMP-0079721-1, "CAP, CERM, 0.01 µF, 25 V,+/- 10%, X7R, 0603", Cap_Case=0603, Manufacturer="Presidio Components", TempCo=X7R, Tolerance_%=10%, Value2=25V, ValueDisplayed=0.01µF
C29 C30: library part CMP-0084680-1, "CAP, CERM, 22 µF, 25 V,+/- 20%, X5R, AEC-Q200 Grade 3, 0805", Cap_Case=0805, Manufacturer=MuRata, TempCo=X5R, Tolerance_%=20%, Value2=25V, ValueDisplayed=22µF
C31: library part CMP-0750159-1, "CAP, AL, 47 µF, 25 V, +/- 20%, 0.05 ohm, AEC-Q200 Grade 1, SMD", Cap_Case=6.3x5.8mm, Manufacturer=Chemi-Con, Tolerance_%=20%, Value1="0.05 ohm", Value2=25V, ValueDisplayed=47µF
D1 D4: library part CMP-0077081-1, "Diode, Ultrafast, 1200 V, 1 A, SMA", Manufacturer=STMicroelectronics, Supplier Part Number 1=497-8048-1-ND, Value1=1A, Value2=1.9V
D2 D3: library part CMP-0002874-1, "LED, Green, SMD", Color=green, Manufacturer=OSRAM, Supplier Part Number 1=475-2709-1-ND, Value1=W, Value2=1.7V
H1 H2 H3 H5: library part CMP-0003610-1, "Standoff, Hex, 0.5\"L #4-40 Nylon", Manufacturer=Keystone, Supplier Part Number 1=36-1902C-ND
H4 H6 H7 H8: library part CMP-0003617-1, "Machine Screw, Round, #4-40 x 1/4, Nylon, Philips panhead", Manufacturer="B&F Fastener Supply", Supplier Part Number 1=H542-ND
J1 J3 J4: library part CMP-0075484-1, "Header, 100mil, 3x1, Gold, TH", Manufacturer=Samtec, Supplier Part Number 1=HTSW-103-07-G-S-ND
J2: library part CMP-0055096-2, "Header, 2.54 mm, 4x2, Gold, TH", Color=Black, Manufacturer=Mill-Max, Supplier Part Number 1=ED1309-08-ND
J5: library part CMP-0092598-1, Current_A=3A, Digikey Part Number=2553-2011-1X02G00SB-ND, Manufacturer=Oupiin, Operating Temperature Range="-40°C to +105°C", Voltage_V=150V
J6 J7: library part CMP-0055713-1, "Receptacle, 2.54mm, 2x2, Gold, TH", Color=Black, Current_A=4.7A, Manufacturer=Samtec, Supplier Part Number 1=SAM1208-02-ND, Voltage_V=465V
Logo1: library part CMP-0074838-1, "Texas Instrument Corporate Signature"
LOGO2: library part CMP-0074835-1, "IEC 61010-1 High Voltage Warning"
Logo3: library part CMP-0074837-2, "IEC 61010-1 Hot Surface Warning", Manufacturer="Texas Instruments"
Q1: library part CMP-0000739-1, "MOSFET, N-CH, 40 V, 5.6 A, SOT-23", Alternate Manufacturer=None, Manufacturer=Vishay-Siliconix, Supplier Part Number 1=SI2318CDS-T1-GE3CT-ND, Value1=0.05, Value2="5.8 nC"
R1: library part CMP-0026758-1, "RES, 2.20 k, 1%, 0.063 W, AEC-Q200 Grade 0, 0402", Manufacturer="Stackpole Electronics Inc", Power_W=63mW, Supplier Part Number 1=RMCF0402FT2K20CT-ND, TempCo="100 ppm/C", Tolerance_%=1%, Value2=0.063W, Value_Code=2k20, ValueDisplayed=2.20k
R2: library part CMP-0025813-4, "RES, 470, 5%, 0.1 W, AEC-Q200 Grade 0, 0603", Manufacturer=Vishay-Dale, Power_W=100mW, Supplier Part Number 1=541-470GCT-ND, TempCo="200 ppm/C", Tolerance_%=5%, Value2=0.1W, Value_Code=470R, ValueDisplayed=470
R3: library part CMP-0023730-2, "RES, 13.2 k, 0.1%, 0.1 W, 0603", Manufacturer="Yageo America", Power_W=100mW, TempCo="25 ppm/C", Tolerance_%=0.1%, Value2=0.1W, Value_Code=13k2, ValueDisplayed=13.2k
R4: library part CMP-0025564-2, "RES, 77.7 k, 0.5%, 0.1 W, 0603", Manufacturer="Yageo America", Power_W=100mW, TempCo="50 ppm/C", Tolerance_%=0.5%, Value2=0.1W, Value_Code=77k7, ValueDisplayed=77.7k
R5 R6 R8: library part CMP-0021998-4, "RES, 10.0 k, 1%, 0.1 W, AEC-Q200 Grade 0, 0603", Manufacturer=Vishay-Dale, Power_W=100mW, Supplier Part Number 1=541-10.0KHCT-ND, TempCo="100 ppm/C", Tolerance_%=1%, Value2=0.1W, Value_Code=10k0, ValueDisplayed=10.0k
R7: library part CMP-0022692-3, "RES, 22.0 k, 1%, 0.1 W, AEC-Q200 Grade 0, 0603", Manufacturer=Panasonic, Power_W=100mW, Supplier Part Number 1=P22.0KHCT-ND, TempCo="100 ppm/C", Tolerance_%=1%, Value2=0.1W, Value_Code=22k0, ValueDisplayed=22.0k
R9: library part CMP-0026926-3, "RES, 3.3, 5%, 0.063 W, AEC-Q200 Grade 0, 0402", Manufacturer=Vishay-Dale, Power_W=63mW, Supplier Part Number 1=541-3.3JCT-ND, TempCo="200 ppm/C", Tolerance_%=5%, Value2=0.063W, Value_Code=3R30, ValueDisplayed=3.3
R10: library part CMP-0026754-1, "RES, 10.0 k, 1%, 0.063 W, AEC-Q200 Grade 0, 0402", Manufacturer="Stackpole Electronics Inc", Power_W=63mW, Supplier Part Number 1=RMCF0402FT10K0CT-ND, TempCo="100 ppm/C", Tolerance_%=1%, Value2=0.063W, Value_Code=10k0, ValueDisplayed=10.0k
R11 R14: library part CMP-0083047-1, "RES, 2.20, 1%, 0.5 W, 1210", Manufacturer=Yageo, Power_W=500mW, TempCo="200 ppm/C", Tolerance_%=1%, Value2=0.5W, Value_Code=2R20, ValueDisplayed=2.20
R13: library part CMP-0026512-2, "RES, 6.04 k, 1%, 0.063 W, AEC-Q200 Grade 0, 0402", Manufacturer=Vishay-Dale, Power_W=63mW, Supplier Part Number 1=541-6.04KLCT-ND, TempCo="100 ppm/C", Tolerance_%=1%, Value2=0.063W, Value_Code=6k04, ValueDisplayed=6.04k
R15 R16: library part CMP-0026414-2, "RES, 4.99 k, 1%, 0.063 W, AEC-Q200 Grade 0, 0402", Manufacturer=Vishay-Dale, Power_W=63mW, Supplier Part Number 1=541-4.99KLCT-ND, TempCo="100 ppm/C", Tolerance_%=1%, Value2=0.063W, Value_Code=4k99, ValueDisplayed=4.99k
R17: library part CMP-0026797-1, "RES, 10.0 k, 0.1%, 0.063 W, 0402", Manufacturer="TT Electronics/IRC", Power_W=63mW, Supplier Part Number 1=985-1366-1-ND, TempCo="10 ppm/C", Tolerance_%=0.1%, Value2=0.063W, Value_Code=10k0, ValueDisplayed=10.0k
R18: library part CMP-0024995-2, "RES, 25.8 k, 0.5%, 0.1 W, 0603", Manufacturer="Yageo America", Power_W=100mW, TempCo="50 ppm/C", Tolerance_%=0.5%, Value2=0.1W, Value_Code=25k8, ValueDisplayed=25.8k
R20: library part CMP-0025701-4, "RES, 10 k, 5%, 0.1 W, AEC-Q200 Grade 0, 0603", Manufacturer=Vishay-Dale, Power_W=100mW, Supplier Part Number 1=541-10KGCT-ND, TempCo="200 ppm/C", Tolerance_%=5%, Value2=0.1W, Value_Code=10k0, ValueDisplayed=10k
R22 R23: library part CMP-0025951-2, "RES, 100, 1%, 0.063 W, 0402", Manufacturer=Vishay-Dale, PartNumber=CRCW0402100RFKED, Power_W=63mW, Supplier Part Number 1=541-100LCT-ND, TempCo="100 ppm/C", Tolerance_%=1%, Value2=0.063W, Value_Code=100R, ValueDisplayed=100
R25: library part CMP-0026992-3, "RES, 0, 5%, 0.1 W, AEC-Q200 Grade 0, 0402", Manufacturer=Panasonic, Power_W=100mW, Supplier Part Number 1=P0.0JCT-ND, TempCo="600 ppm/C", Tolerance_%=5%, Value2=0.1W, Value_Code=0000, ValueDisplayed=0
R26: library part CMP-0080488-1, "RES, 10.0 k, 1%, 0.1 W, 0603", Manufacturer="TT Electronics/IRC", Power_W=100mW, TempCo="100 ppm/C", Tolerance_%=1%, Value2=0.1W, Value_Code=10k0, ValueDisplayed=10.0k
R28: library part CMP-0026402-2, "RES, 499, 1%, 0.063 W, AEC-Q200 Grade 0, 0402", Manufacturer=Vishay-Dale, Power_W=63mW, Supplier Part Number 1=541-499LCT-ND, TempCo="100 ppm/C", Tolerance_%=1%, Value2=0.063W, Value_Code=499R, ValueDisplayed=499
R31: library part CMP-0024922-3, "RES, 20.0 k, 0.5%, 0.1 W, 0603", Manufacturer="Yageo America", Power_W=100mW, TempCo="50 ppm/C", Tolerance_%=0.5%, Value2=0.1W, Value_Code=20k0, ValueDisplayed=20.0k
R40: library part CMP-0022559-4, "RES, 6.19 k, 1%, 0.1 W, AEC-Q200 Grade 0, 0603", Manufacturer=Vishay-Dale, Power_W=100mW, Supplier Part Number 1=541-6.19KHCT-ND, TempCo="100 ppm/C", Tolerance_%=1%, Value2=0.1W, Value_Code=6k19, ValueDisplayed=6.19k
TP1 TP17: library part CMP-0055142-2, "Test Point, Compact, Red, TH", Color=Red, Manufacturer="Keystone Electronics", PartNumber=5005, Supplier Part Number 1=36-5005-ND
TP2 TP20: library part CMP-0055143-2, "Test Point, Compact, Black, TH", Color=Black, Manufacturer="Keystone Electronics", PartNumber=5006, Supplier Part Number 1=36-5006-ND
TP3: library part CMP-0055142-2, "Test Point, Compact, Red, TH", Color=Red, Manufacturer="Keystone Electronics", Supplier Part Number 1=36-5005-ND
TP4 TP10: library part CMP-0055143-2, "Test Point, Compact, Black, TH", Color=Black, Manufacturer="Keystone Electronics", Supplier Part Number 1=36-5006-ND
TP5 TP6 TP8 TP11 TP12 TP13 TP15 TP16: library part CMP-0055027-1, "PCB Pin, 20mil Dia, Gold, TH", Manufacturer=Mill-Max, PartNumber=0508-0-00-15-00-00-03-0, Supplier Part Number 1=ED90418-ND
TP7: library part CMP-0055144-2, "Test Point, Compact, White, TH", Color=White, Manufacturer="Keystone Electronics", Supplier Part Number 1=36-5007-ND
TP9: library part CMP-0055146-2, "Test Point, Compact, Yellow, TH", Color=Yellow, Manufacturer="Keystone Electronics", Supplier Part Number 1=36-5009-ND
TP14: library part CMP-0055145-2, "Test Point, Compact, Orange, TH", Color=Orange, Manufacturer="Keystone Electronics", Supplier Part Number 1=36-5008-ND
U1: library part CMP-0095031-1, "Linear Voltage Regulator IC Positive Fixed 1 Output 150mA 8-SON (3x3)", Digikey Part Number=296-TPS7B8450QWDRBRQ1CT-ND, Dropout Voltage=155mV, Manufacturer="Texas Instruments", Max Supply Voltage=40V, Min Supply Voltage=5.155V, Mouser Part Number=595-PS7B8450QWDRBRQ1, Nominal Supply Current=18uA, Operating Temperature Range="-40°C to +150°C", Output Voltage=5V
U2: library part CMP-0089786-7, "2W, 24V-Vin, 25V-Vout, High-Efficiency, >2. 5 kVRMS Isolated DC-DC Converter", Manufacturer="Texas Instruments", Max Supply Voltage=27V, Min Supply Voltage=21V, Operating Temperature Range="-40°C to +150°C", Output Voltage=18-25/2.5-25V
U3: library part CMP-0080536-2, "Single Channel Isolated Gate Driver for SiC/IGBT with Advanced Protection and High-CMTI, DW0016B (SOIC-16)", Alternate Manufacturer="Texas Instruments", Alternate PartNumber=UCC21732QDWQ1

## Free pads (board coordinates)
  round 60 hole 30: 2(2578.74,733.26) 3(2578.74,814.7)

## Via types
v1: diameter 20, hole 10, Top Layer 1 to Bottom Layer 1, tented top, 54 vias
v2: diameter 20, hole 10, Top Layer 1 to Bottom Layer 1, 41 vias
v3: diameter 18, hole 10, Top Layer 1 to Bottom Layer 1, tented both sides, 9 vias
v4: diameter 18, hole 10, Top Layer 1 to Bottom Layer 1, 4 vias
v5: diameter 19.68, hole 7.87, Top Layer 1 to Bottom Layer 1, 4 vias
v6: diameter 50, hole 28, Top Layer 1 to Bottom Layer 1, 3 vias

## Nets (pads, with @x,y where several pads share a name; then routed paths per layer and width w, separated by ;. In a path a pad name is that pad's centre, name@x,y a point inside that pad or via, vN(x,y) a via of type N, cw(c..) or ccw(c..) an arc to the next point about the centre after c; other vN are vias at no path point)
APWM: C26.1 J2.6 R31.2 | length 1062.3
  Top Layer 1 w20: J2.6@153.09,646.63 210.53,589.19 210.53,467.64 467.29,210.88 C26.1@897.16,210.88 897.16,206.94 903.06,201.03 R31.2@957.28,201.03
